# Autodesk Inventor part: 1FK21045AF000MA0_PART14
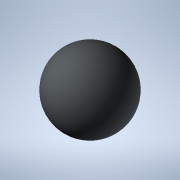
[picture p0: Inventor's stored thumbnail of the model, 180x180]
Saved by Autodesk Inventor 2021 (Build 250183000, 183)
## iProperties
Created: 2025-04
Part Number: 1FK21045AF000MA0_PART14
Material: Generic
Catalog Web Link: www.3dfindit.com
Description: -Servo synchronous motor
Document SubType Name: Modeling
Designer: psAdmin
Mass: 0.137258 g
Surface Area: 1.2868 cm^2
Volume: 0.137258 cm^3
Density: 1 g/cm^3
Appearance: PSOLRGB-212-217-219
Category: PARTsolutions
Title: 1FK21045AF000MA0_PART14
Author: Cadenas PARTsolutions
Comments: Servo synchronous motor
Sending System: PARTsolutions
Preprocessor: ST-DEVELOPER v19.3
PSOL_IDENT_0: {$CADENAS_DATA/23d-libs/siemens_ag/_cat_/8b/0a/1fk21045af000ma0.prj},216 {VTYP=3D},{NB=1FK21045AF000
PSOL_IDENT_1: MA0_PART14},{LINA=1FK21045AF000MA0_PART14},{NN=1FK21045AF000MA0_PART14},{NOPRJ=TRUE},{DATE=19.08.202
PSOL_IDENT_2: 5 14:00:48},{GEOMDATE=30.07.2025 02:00:28},{VERSION=},{LINEID=10},{WBVAR=},{WBNUMERIC=}  {NB=1FK2104
PSOL_IDENT_3: 5AF000MA0_PART14},{LINA=1FK21045AF000MA0_PART14},{KT=DUMMY},{PREVIEW=../../../_pool_/a9/69/p_d211_xx
PSOL_IDENT_4: _00818j.png},{DESCSHORT=SIMOTICS S-1FK2 HD, SINAMICS S210 3AC 400V-480V, 2.4 Nm, 3000 rpm},{DESCLONG=
PSOL_IDENT_5: SIMOTICS S-1FK2 HD servo motor M0=2.4 Nm; PN = 0.75 kW at nN=3000 rpm (380-480 V); PN = 0.375 kW at
PSOL_IDENT_6: nN=1500 rpm (200-240 V); degree of protection IP64; cylindrical shaft D19x40mm; absolute encoder 22-
PSOL_IDENT_7: bit + 12-bit multiturn (encoder AM22DQC); with OCC interface; plug size M17, rotatable; SIMOTICS S-1
PSOL_IDENT_8: FK2 servomotorfor a wide range of uses in industrial environments. SIMOTICS S‑1FK2 servomotors are c
PSOL_IDENT_9: ompact synchronous motors with a high dynamic performance that set themselves apart as a result of t
PSOL_IDENT_10: heir high power density, degree of protection and overload capability. The motors are available in t
PSOL_IDENT_11: wo variants: as High Dynamic variant (highest dynamic performance as a result of the low intrinsic m
PSOL_IDENT_12: oment of inertia for applications demanding a high dynamic performance with low moved masses) - and
PSOL_IDENT_13: as Compact variant (precise and stable closed-loop control for medium up to large moved masses as a
PSOL_IDENT_14: result of a medium intrinsic moment of inertia). SIMOTICSS‑1FK2 servomotors fully exploit their stre
PSOL_IDENT_15: ngths in a system with the SINAMICSS210 frequency converter and simple connection using the one cabl
PSOL_IDENT_16: e connection (OCC). Advantages include the short control and positioning times, fast and precise cor
PSOL_IDENT_17: rection of disturbing quantities as well as stable control with a high dynamic performance. The serv
PSOL_IDENT_18: o motors can be configured to address a wide range of requirements. For example with and without hol
PSOL_IDENT_19: ding brake, IP64 or IP65 degree of protection, singleturn or multiturn absolute encoders - to name j
PSOL_IDENT_20: ust a few. Further, the servomotors are available in different shaft heights extending from 20 to 10
PSOL_IDENT_21: 0. A shaft sealing ring is available to achieve an IP65 degree of protection and for subsequent moun
PSOL_IDENT_22: ting at the motor or as spare part. SIMOTICS - the optimum motor for each and every motion control a
PSOL_IDENT_23: pplication.},{INTNO=195125050112},{SUPPLIERALTNO=1FK2104-5AF00-0MA0},{MANUID=1FK21045AF000MA0},{MANU
PSOL_IDENT_24: NAME=Siemens},{MANUTYPEDESC=Synchronous motor 1FK2-HD 2.4 NM},{AAU732=SIMOTICS},{AAO057=S-1FK2},{AAU
PSOL_IDENT_25: 734=SIMOTICS S-1FK2 HD servo motor M0=2.4 Nm; PN = 0.75 kW at nN=3000 rpm (380-480 V); PN = 0.375 kW
PSOL_IDENT_26: at nN=1500 rpm (200-240 V); degree of protection IP64; cylindrical shaft D19x40mm; absolute encoder
PSOL_IDENT_27: 22-bit + 12-bit multiturn (encoder AM22DQC); with OCC interface; plug size M17, rotatable;},{AAW338=
PSOL_IDENT_28: Synchronous motor 1FK2-HD 2.4 NM},{AAO742=SIMOTICS},{AAO663=4042948692912},{NOCUPEROU=1},{PRICEQUANT
PSOL_IDENT_29: ITY=1},{QUANTITYMIN=1},{QUANTITYINT=1},{CTN=85015100},{COO=DE},{AAO676=1FK2104-5AF00-0MA0},{AAO677=S
PSOL_IDENT_30: iemens AG},{ORDERUNIT=C62},{CONTENTUNIT=C62}
NB: 1FK21045AF000MA0_PART14
NT: Servo synchronous motor
NBSYN: $MANUID._PART14
LINA: 1FK21045AF000MA0_PART14
CATALOG: SIEMENS
PREVIEW: ../../../_pool_/a9/69/p_d211_xx_00818j.png
DESCSHORT: SIMOTICS S-1FK2 HD, SINAMICS S210 3AC 400V-480V, 2.4 Nm, 3000 rpm
DESCLONG: SIMOTICS S-1FK2 HD servo motor M0=2.4 Nm; PN = 0.75 kW at nN=3000 rpm (380-480 V); PN = 0.375 kW at nN=1500 rpm (200-240 V); degree of protection IP64; cylindri
INTNO: 195125050112
SUPPLIERALTNO: 1FK2104-5AF00-0MA0
MANUID: 1FK21045AF000MA0
MANUNAME: Siemens
MANUTYPEDESC: Synchronous motor 1FK2-HD 2.4 NM
AAU732: SIMOTICS
AAO057: S-1FK2
AAU734: SIMOTICS S-1FK2 HD servo motor M0=2.4 Nm; PN = 0.75 kW at nN=3000 rpm (380-480 V); PN = 0.375 kW at nN=1500 rpm (200-240 V); degree of protection IP64; cylindri
AAW338: Synchronous motor 1FK2-HD 2.4 NM
AAO742: SIMOTICS
AAO663: 4042948692912.0
NOCUPEROU: 1
PRICEQUANTITY: 1
QUANTITYMIN: 1
QUANTITYINT: 1
CTN: 85015100
COO: DE
ARTICLENO: 1FK21045AF000MA0_PART14
BOMINFO: 1FK21045AF000MA0_PART14
CREATOR: CADENAS GmbH
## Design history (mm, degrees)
feature "2025_04_17_15_40_42_0766"
body "Solid1"
